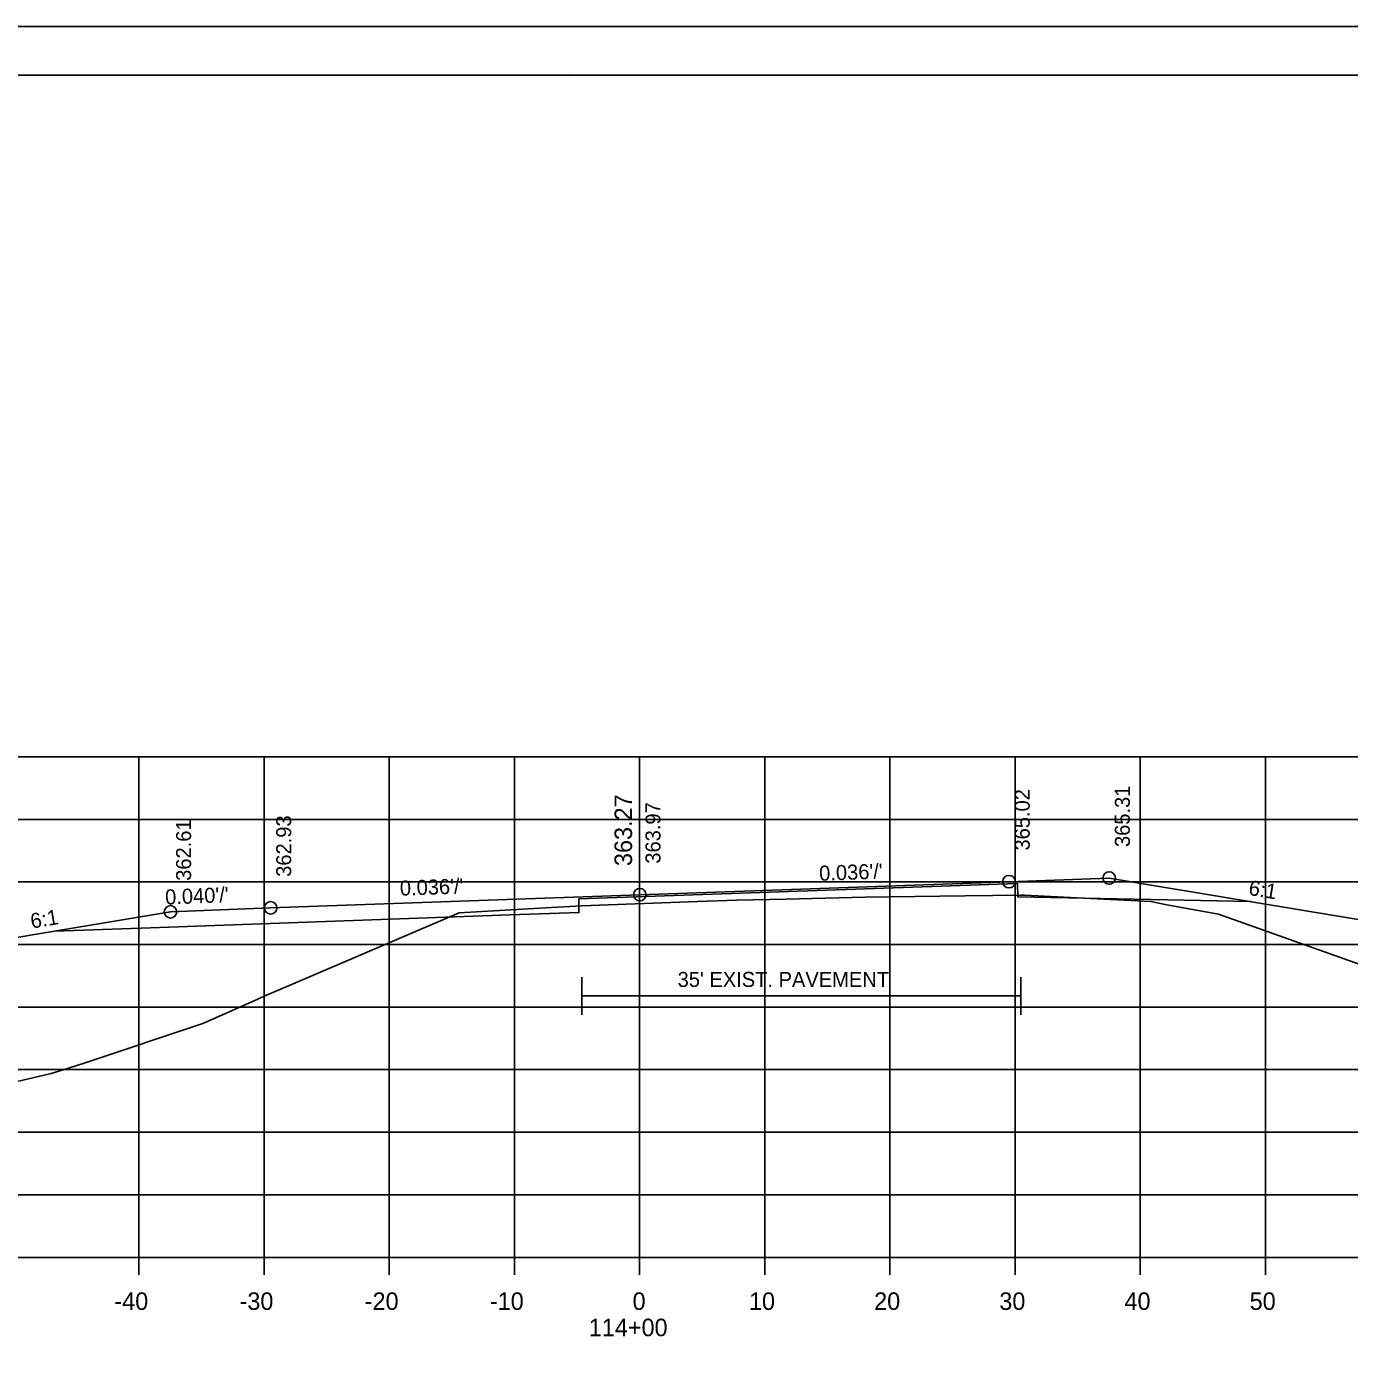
# Model space of a CAD drawing. Extents: x 1374859 to 1376773, y 382242 to 389804.
# Drawn here: x 1376561.5 to 1376667.2, y 383202.5 to 383308.4 of the extents above; entities that cross this region are included whole.
import ezdxf

# ---------------------------------------------------------------- set-up
doc = ezdxf.new("R2010")
doc.units = 0
for name, color, linetype in [('R_Axis', 7, 'Continuous'), ('R_Axis Annot', 7, 'Continuous'), ('R_Border', 7, 'Continuous'), ('R_Border Notes', 7, 'Continuous'), ('R_Exist Surface', 7, 'Continuous'), ('R_Fin Surface', 7, 'Continuous'), ('R_Grid', 7, 'Continuous'), ('R_No Plot', 7, 'Continuous'), ('R_Xsect Elev', 7, 'Continuous'), ('R_Xsect Slope', 7, 'Continuous')]:
    doc.layers.add(name, color=color, linetype=linetype)

msp = doc.modelspace()

# ---------------------------------------------------------------- linework, layer by layer
at = {"layer": 'R_Axis'}
for p, q in [((1376470.45, 383210.07), (1376750.45, 383210.07)), ((1376570.45, 383208.67), (1376570.45, 383210.07)), ((1376580.45, 383208.67), (1376580.45, 383210.07)), ((1376590.45, 383208.67), (1376590.45, 383210.07)), ((1376600.45, 383208.67), (1376600.45, 383210.07)), ((1376610.45, 383208.67), (1376610.45, 383210.07)), ((1376620.45, 383208.67), (1376620.45, 383210.07)), ((1376630.45, 383208.67), (1376630.45, 383210.07)), ((1376640.45, 383208.67), (1376640.45, 383210.07)), ((1376650.45, 383208.67), (1376650.45, 383210.07)), ((1376660.45, 383208.67), (1376660.45, 383210.07))]:
    msp.add_line(p, q, dxfattribs=at)
at = {"layer": 'R_Border'}
for p, q in [((1376452.45, 383304.53), (1376768.63, 383304.53)), ((1376604.97, 383304.27), (1376604.97, 383304.27)), ((1376604.97, 383304.27), (1376604.97, 383304.27))]:
    msp.add_line(p, q, dxfattribs=at)
at = {"layer": 'R_Border Notes'}
for points in [[(1376605.83, 383232.46), (1376605.83, 383229.46)], [(1376640.92, 383232.46), (1376640.92, 383229.46)], [(1376605.83, 383230.96), (1376640.92, 383230.96)]]:
    msp.add_lwpolyline(points, dxfattribs=at)
at = {"layer": 'R_Exist Surface'}
msp.add_lwpolyline([(1376556.98, 383223.24), (1376563.45, 383224.76), (1376564.75, 383225.16), (1376566.15, 383225.61), (1376575.55, 383228.76), (1376579.94, 383230.71), (1376579.99, 383230.73), (1376580.23, 383230.83), (1376596.04, 383237.6), (1376602.94, 383238), (1376605.83, 383238.16), (1376615.09, 383238.52), (1376618.2, 383238.62), (1376622.13, 383238.7), (1376628.47, 383238.84), (1376636.43, 383238.96), (1376640.92, 383239), (1376641.19, 383239.02), (1376645.95, 383238.78), (1376651.3, 383238.5), (1376652.58, 383238.25), (1376656.69, 383237.5), (1376673.19, 383231.64)], dxfattribs=at)
at = {"layer": 'R_Fin Surface'}
for points in [[(1376498.31, 383220.65), (1376504.59, 383218.55), (1376550.97, 383234.01), (1376563.71, 383236.14), (1376572.97, 383237.68), (1376580.97, 383238), (1376610.47, 383239.05), (1376639.97, 383240.09), (1376647.97, 383240.38), (1376659.51, 383238.45), (1376669.97, 383236.71), (1376712.38, 383222.57), (1376725.33, 383226.89)], [(1376563.71, 383236.14), (1376570.62, 383236.38), (1376600.1, 383237.43), (1376605.6, 383237.62), (1376605.61, 383238.71), (1376640.65, 383239.95)], [(1376640.65, 383239.95), (1376640.66, 383238.87), (1376659.26, 383238.5)]]:
    msp.add_lwpolyline(points, dxfattribs=at)
at = {"layer": 'R_Grid'}
for p, q in [((1376470.45, 383250.07), (1376750.45, 383250.07)), ((1376570.45, 383210.07), (1376570.45, 383250.07)), ((1376580.45, 383210.07), (1376580.45, 383250.07)), ((1376590.45, 383210.07), (1376590.45, 383250.07)), ((1376600.45, 383210.07), (1376600.45, 383250.07)), ((1376610.45, 383210.07), (1376610.45, 383250.07)), ((1376620.45, 383210.07), (1376620.45, 383250.07)), ((1376630.45, 383210.07), (1376630.45, 383250.07)), ((1376640.45, 383210.07), (1376640.45, 383250.07)), ((1376650.45, 383210.07), (1376650.45, 383250.07)), ((1376660.45, 383210.07), (1376660.45, 383250.07)), ((1376470.45, 383245.07), (1376750.45, 383245.07)), ((1376470.45, 383240.07), (1376750.45, 383240.07)), ((1376470.45, 383235.07), (1376750.45, 383235.07)), ((1376470.45, 383230.07), (1376750.45, 383230.07)), ((1376470.45, 383225.07), (1376750.45, 383225.07)), ((1376470.45, 383220.07), (1376750.45, 383220.07)), ((1376470.45, 383215.07), (1376750.45, 383215.07)), ((1376470.45, 383210.07), (1376750.45, 383210.07))]:
    msp.add_line(p, q, dxfattribs=at)
at = {"layer": 'R_No Plot'}
msp.add_line((1376440.05, 383308.43), (1376773.38, 383308.43), dxfattribs=at)
for points in [[(1376440.04, 383308.43), (1376773.38, 383308.43), (1376773.38, 383095.09), (1376440.04, 383095.09)], [(1376686.37, 383304.53), (1376686.37, 383294.65), (1376722.1, 383294.65), (1376722.1, 383291.73), (1376745.3, 383291.73), (1376745.3, 383267.4), (1376768.63, 383267.4), (1376768.63, 383099.07), (1376452.45, 383099.07), (1376452.45, 383304.53)]]:
    msp.add_lwpolyline(points, close=True, dxfattribs=at)
for centre in [(1376647.97, 383240.38), (1376639.97, 383240.09), (1376610.47, 383239.05), (1376572.97, 383237.68), (1376580.97, 383238)]:
    msp.add_circle(centre, 0.5, dxfattribs=at)

# ---------------------------------------------------------------- texts
at = {"layer": 'R_Axis Annot'}
for s, p in [('-40', (1376568.49, 383205.87)), ('-30', (1376578.49, 383205.87)), ('-20', (1376588.49, 383205.87)), ('-10', (1376598.49, 383205.87)), ('0', (1376609.89, 383205.87)), ('10', (1376619.19, 383205.87)), ('20', (1376629.19, 383205.87)), ('30', (1376639.19, 383205.87)), ('40', (1376649.19, 383205.87)), ('50', (1376659.19, 383205.87)), ('114+00', (1376606.39, 383203.77))]:
    msp.add_text(s, height=1.4, dxfattribs=at).set_placement(p)
at = {"layer": 'R_Border Notes'}
msp.add_text("35' EXIST. PAVEMENT", height=1.2, rotation=0, dxfattribs=at).set_placement((1376613.49, 383231.68))
at = {"layer": 'R_Xsect Elev'}
for s, height, p in [('365.02', 1.2, (1376641.62, 383242.58)), ('365.31', 1.2, (1376649.62, 383242.86)), ('363.27', 1.4, (1376609.85, 383241.34)), ('363.97', 1.2, (1376612.12, 383241.53)), ('362.61', 1.2, (1376574.62, 383240.16)), ('362.93', 1.2, (1376582.62, 383240.48))]:
    msp.add_text(s, height=height, rotation=90, dxfattribs=at).set_placement(p)
at = {"layer": 'R_Xsect Slope'}
for s, rotation, p in [("0.036'/'", 2.0335, (1376624.82, 383240.16)), ("0.040'/'", 2.2906, (1376572.57, 383238.26)), ("0.036'/'", 2.0335, (1376591.32, 383238.97)), ('6:1', 350.5358, (1376659.05, 383239.04)), ('6:1', 9.4642, (1376561.89, 383236.34))]:
    msp.add_text(s, height=1.2, rotation=rotation, dxfattribs=at).set_placement(p)

doc.saveas('drawing.dxf')
